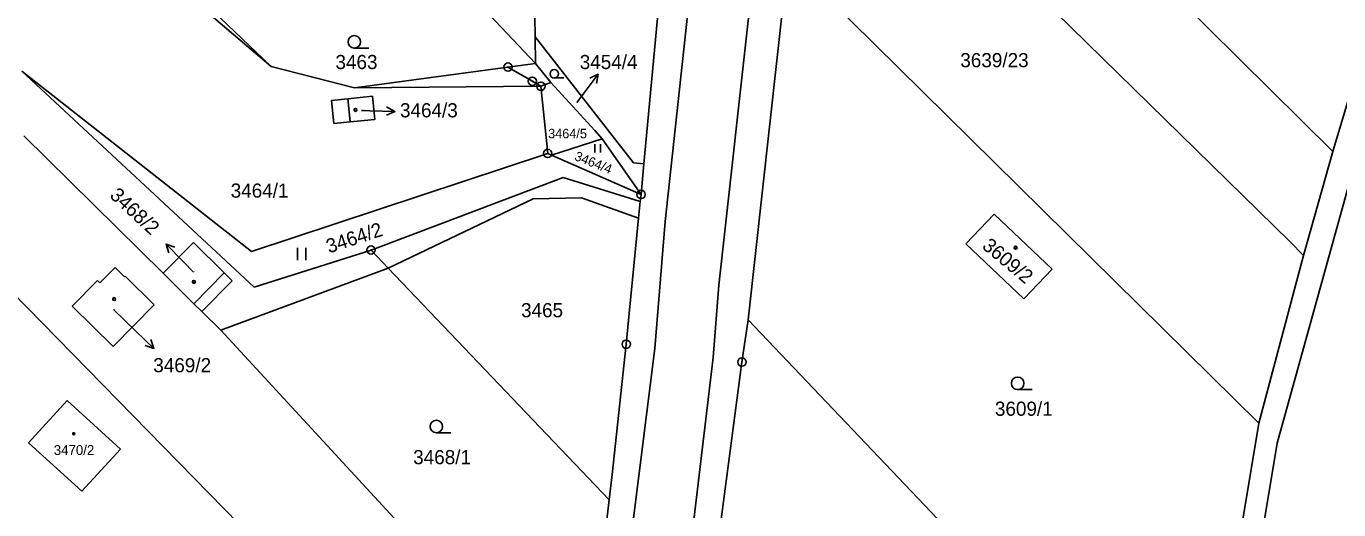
# Model space of a CAD drawing. Extents: x -593183 to -588034, y -1130415 to -1124994.
# Drawn here: x -592488.1 to -592330.3, y -1129087.1 to -1129029 of the extents above; entities that cross this region are included whole.
import ezdxf

# ---------------------------------------------------------------- set-up
doc = ezdxf.new("R2010")
doc.units = 0
for name, color, linetype in [('Vrstva 1', 7, 'Continuous'), ('Vrstva 16', 7, 'Continuous'), ('Vrstva 18', 7, 'Continuous'), ('Vrstva 19', 7, 'Continuous'), ('Vrstva 24', 7, 'Continuous'), ('Vrstva 25', 7, 'Continuous'), ('Vrstva 4', 7, 'Continuous')]:
    doc.layers.add(name, color=color, linetype=linetype)

msp = doc.modelspace()

# ---------------------------------------------------------------- linework, layer by layer
at = {"layer": 'Vrstva 1'}
for p, q in [((-592394.86, -1128997.4), (-592336.19, -1129054.85)), ((-592427.3, -1129008.83), (-592426.94, -1129030.23)), ((-592482.97, -1129010.56), (-592458.71, -1129033.8)), ((-592363.73, -1129011.6), (-592331.01, -1129044.04)), ((-592479.35, -1129016.2), (-592458.71, -1129033.8)), ((-592411.34, -1129018.3), (-592413.86, -1129045.5)), ((-592396.54, -1129020.85), (-592401.33, -1129064.26)), ((-592396.54, -1129020.85), (-592339.92, -1129076.67)), ((-592322.01, -1129022.47), (-592337.72, -1129079.08)), ((-592435.34, -1129024.51), (-592426.88, -1129033.44)), ((-592426.88, -1129033.44), (-592426.94, -1129030.23)), ((-592426.94, -1129030.23), (-592415.12, -1129045.38)), ((-592326.97, -1129030.51), (-592331.01, -1129044.04)), ((-592430.21, -1129033.89), (-592426.88, -1129033.44)), ((-592426.88, -1129033.44), (-592425.06, -1129035.74)), ((-592488.69, -1129034.36), (-592461.07, -1129056.03)), ((-592488.69, -1129034.36), (-592460.74, -1129060.34)), ((-592458.71, -1129033.8), (-592448.68, -1129036.38)), ((-592448.68, -1129036.38), (-592430.21, -1129033.89)), ((-592430.21, -1129033.89), (-592427.28, -1129035.58)), ((-592427.28, -1129035.58), (-592426.25, -1129036.18)), ((-592426.25, -1129036.18), (-592425.43, -1129044.26)), ((-592419.78, -1129041.5), (-592425.06, -1129035.74)), ((-592451.45, -1129037.88), (-592449.46, -1129037.68)), ((-592451.17, -1129040.67), (-592451.45, -1129037.88)), ((-592449.46, -1129037.68), (-592446.52, -1129037.39)), ((-592446.52, -1129037.39), (-592446.24, -1129040.18)), ((-592449.18, -1129040.47), (-592451.17, -1129040.67)), ((-592446.24, -1129040.18), (-592449.18, -1129040.47)), ((-592488.43, -1129042.16), (-592471.69, -1129058.66)), ((-592424.97, -1129044.46), (-592418.89, -1129042.51)), ((-592418.89, -1129042.51), (-592419.78, -1129041.5)), ((-592414.2, -1129049.19), (-592418.89, -1129042.51)), ((-592461.07, -1129056.03), (-592425.43, -1129044.26)), ((-592425.43, -1129044.26), (-592424.97, -1129044.46)), ((-592424.97, -1129044.46), (-592414.2, -1129049.19)), ((-592331.01, -1129044.04), (-592334.54, -1129056.54)), ((-592413.86, -1129045.5), (-592415.12, -1129045.38)), ((-592413.86, -1129045.5), (-592414.2, -1129049.19)), ((-592446.68, -1129055.86), (-592423.56, -1129047.13)), ((-592423.56, -1129047.13), (-592414.32, -1129050.02)), ((-592414.2, -1129049.19), (-592414.32, -1129050.02)), ((-592414.32, -1129050.02), (-592414.51, -1129052.02)), ((-592414.51, -1129052.02), (-592415.99, -1129067.18)), ((-592371.74, -1129051.54), (-592375.15, -1129055.13)), ((-592364.77, -1129058.17), (-592371.74, -1129051.54)), ((-592471.69, -1129058.66), (-592468.04, -1129054.95)), ((-592468.04, -1129054.95), (-592464.34, -1129058.6)), ((-592375.15, -1129055.13), (-592368.16, -1129061.73)), ((-592336.19, -1129054.85), (-592334.54, -1129056.54)), ((-592460.74, -1129060.34), (-592446.68, -1129055.86)), ((-592446.68, -1129055.86), (-592444.62, -1129058.03)), ((-592334.54, -1129056.54), (-592339.92, -1129076.67)), ((-592493.1, -1129057.61), (-592423.6, -1129128.47)), ((-592479.28, -1129059.82), (-592477.47, -1129057.96)), ((-592477.47, -1129057.96), (-592476.34, -1129059.08)), ((-592467.99, -1129062.31), (-592471.69, -1129058.66)), ((-592464.34, -1129058.6), (-592463.38, -1129059.55)), ((-592444.62, -1129058.03), (-592418.06, -1129085.89)), ((-592364.77, -1129058.17), (-592368.16, -1129061.73)), ((-592482.62, -1129062.62), (-592479.58, -1129059.53)), ((-592479.58, -1129059.53), (-592479.28, -1129059.82)), ((-592476.34, -1129059.08), (-592476.26, -1129058.99)), ((-592476.26, -1129058.99), (-592472.76, -1129062.44)), ((-592463.38, -1129059.55), (-592467.03, -1129063.25)), ((-592477.71, -1129067.46), (-592482.62, -1129062.62)), ((-592472.76, -1129062.44), (-592477.71, -1129067.46)), ((-592467.03, -1129063.25), (-592467.99, -1129062.31)), ((-592467.03, -1129063.25), (-592464.76, -1129065.49)), ((-592401.33, -1129064.26), (-592402.08, -1129069.33)), ((-592401.33, -1129064.26), (-592347.3, -1129120.89)), ((-592464.76, -1129065.49), (-592421.15, -1129112.65)), ((-592415.99, -1129067.18), (-592417.67, -1129082.82)), ((-592402.08, -1129069.33), (-592405.97, -1129098.98)), ((-592487.86, -1129079.02), (-592483.22, -1129073.94)), ((-592483.22, -1129073.94), (-592476.82, -1129079.78)), ((-592339.92, -1129076.67), (-592347.3, -1129120.89)), ((-592481.47, -1129084.85), (-592487.86, -1129079.02)), ((-592337.72, -1129079.08), (-592341.52, -1129101.98)), ((-592476.82, -1129079.78), (-592481.47, -1129084.85)), ((-592417.67, -1129082.82), (-592418.06, -1129085.89)), ((-592421.15, -1129112.65), (-592418.06, -1129085.89))]:
    msp.add_line(p, q, dxfattribs=at)
at = {"layer": 'Vrstva 16'}
for p, q in [((-592421.94, -1129038.13), (-592421.18, -1129037.13)), ((-592447.84, -1129039.11), (-592446.81, -1129039.13)), ((-592468.02, -1129058.51), (-592469.22, -1129057.29)), ((-592477.64, -1129063), (-592474.95, -1129065.6))]:
    msp.add_line(p, q, dxfattribs=at)
at = {"layer": 'Vrstva 24'}
for centre, radius in [((-592430.21, -1129033.89), 0.5), ((-592430.21, -1129033.89), 0.0327), ((-592427.28, -1129035.58), 0.5), ((-592427.28, -1129035.58), 0.0327), ((-592426.25, -1129036.18), 0.5), ((-592426.25, -1129036.18), 0.0327), ((-592425.43, -1129044.26), 0.5), ((-592425.43, -1129044.26), 0.0327), ((-592414.2, -1129049.19), 0.5), ((-592414.2, -1129049.19), 0.0327), ((-592446.68, -1129055.86), 0.5), ((-592446.68, -1129055.86), 0.0327), ((-592415.99, -1129067.18), 0.5), ((-592415.99, -1129067.18), 0.0327), ((-592402.08, -1129069.33), 0.5), ((-592402.08, -1129069.33), 0.0327)]:
    msp.add_circle(centre, radius, dxfattribs=at)
at = {"layer": 'Vrstva 25'}
for p, q in [((-592446.94, -1129031.6), (-592448.69, -1129031.6)), ((-592421.18, -1129037.13), (-592419.37, -1129034.74)), ((-592423.48, -1129035.19), (-592424.65, -1129035.19)), ((-592446.81, -1129039.13), (-592443.81, -1129039.2)), ((-592419.78, -1129043.13), (-592419.78, -1129044.13)), ((-592419.09, -1129044.13), (-592419.09, -1129043.13)), ((-592469.22, -1129057.29), (-592471.33, -1129055.15)), ((-592455.53, -1129055.6), (-592455.53, -1129057.1)), ((-592454.51, -1129057.1), (-592454.51, -1129055.6)), ((-592474.95, -1129065.6), (-592472.79, -1129067.69)), ((-592367.17, -1129072.63), (-592368.92, -1129072.63)), ((-592437.07, -1129077.82), (-592438.82, -1129077.82))]:
    msp.add_line(p, q, dxfattribs=at)
for points in [[(-592420.37, -1129035.23), (-592419.37, -1129034.74), (-592419.57, -1129035.84)], [(-592444.8, -1129038.67), (-592443.81, -1129039.2), (-592444.82, -1129039.67)], [(-592470.98, -1129056.22), (-592471.33, -1129055.15), (-592470.27, -1129055.51)], [(-592473.16, -1129066.63), (-592472.79, -1129067.69), (-592473.86, -1129067.35)]]:
    msp.add_lwpolyline(points, dxfattribs=at)
for centre, radius in [((-592448.69, -1129030.85), 0.75), ((-592424.65, -1129034.69), 0.503), ((-592448.55, -1129039.03), 0.175), ((-592448.55, -1129039.03), 0.15), ((-592369.16, -1129055.58), 0.175), ((-592369.16, -1129055.58), 0.15), ((-592467.98, -1129059.69), 0.175), ((-592467.98, -1129059.69), 0.15), ((-592477.57, -1129061.76), 0.175), ((-592477.57, -1129061.76), 0.15), ((-592368.92, -1129071.88), 0.75), ((-592438.82, -1129077.07), 0.75), ((-592482.44, -1129077.93), 0.122), ((-592482.44, -1129077.93), 0.105)]:
    msp.add_circle(centre, radius, dxfattribs=at)
at = {"layer": 'Vrstva 4'}
for p, q in [((-592407.66, -1129018.63), (-592411.32, -1129052.45)), ((-592400.3, -1129019.29), (-592404.86, -1129060.09)), ((-592448.68, -1129036.38), (-592426.25, -1129036.18)), ((-592426.25, -1129036.18), (-592425.06, -1129035.74)), ((-592449.46, -1129037.68), (-592449.18, -1129040.47)), ((-592444.62, -1129058.03), (-592427.19, -1129049.72)), ((-592427.19, -1129049.72), (-592421.38, -1129049.6)), ((-592421.38, -1129049.6), (-592414.51, -1129052.02)), ((-592411.32, -1129052.45), (-592412.54, -1129067.71)), ((-592467.99, -1129062.31), (-592464.34, -1129058.6)), ((-592464.76, -1129065.49), (-592444.62, -1129058.03)), ((-592404.86, -1129060.09), (-592405.55, -1129068.79)), ((-592412.54, -1129067.71), (-592419.1, -1129119.75)), ((-592405.55, -1129068.79), (-592411.79, -1129121.13))]:
    msp.add_line(p, q, dxfattribs=at)

# ---------------------------------------------------------------- texts
at = {"layer": 'Vrstva 16'}
for s, p in [('3454/4', (-592421.58, -1129034.12)), ('3464/3', (-592443.2, -1129039.92)), ('3469/2', (-592472.87, -1129070.55))]:
    msp.add_text(s, height=1.7, dxfattribs=at).set_placement(p)
msp.add_text('3468/2', height=1.7, rotation=317.0902, dxfattribs=at).set_placement((-592478.21, -1129049.44))
at = {"layer": 'Vrstva 18'}
for s, height, p in [('3463', 1.7, (-592450.96, -1129034.12)), ('3639/23', 1.7, (-592375.81, -1129033.9)), ('3454/4', 0.1, (-592421.94, -1129038.13)), ('3464/5', 1.14, (-592425.38, -1129042.44)), ('3464/1', 1.7, (-592463.56, -1129049.57)), ('3465', 1.7, (-592428.64, -1129063.94)), ('3609/1', 1.7, (-592371.65, -1129075.78)), ('3468/1', 1.7, (-592441.61, -1129081.6))]:
    msp.add_text(s, height=height, dxfattribs=at).set_placement(p)
for s, height, rotation, p in [('3464/4', 1.14, 338.1265, (-592422.3, -1129045.01)), ('3464/2', 1.7, 18.2268, (-592451.74, -1129056.28))]:
    msp.add_text(s, height=height, rotation=rotation, dxfattribs=at).set_placement(p)
at = {"layer": 'Vrstva 19'}
for s, height, p in [('3464/3', 0.1, (-592447.84, -1129039.11)), ('3468/2', 0.1, (-592468.02, -1129058.51)), ('3469/2', 0.1, (-592477.64, -1129063)), ('3470/2', 1.19, (-592484.83, -1129080.49))]:
    msp.add_text(s, height=height, dxfattribs=at).set_placement(p)
msp.add_text('3609/2', height=1.7, rotation=320.1893, dxfattribs=at).set_placement((-592373.3, -1129055.57))

doc.saveas('drawing.dxf')
